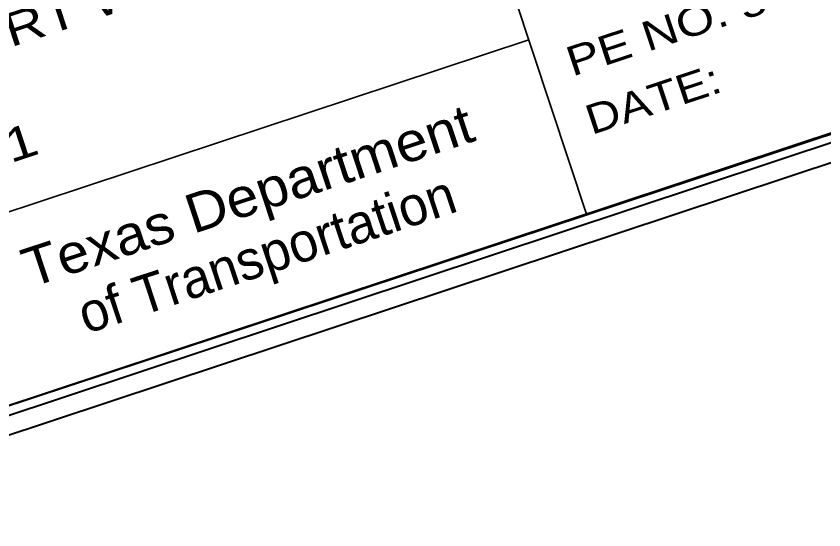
# Model space of a CAD drawing. Extents: x 2355803 to 2371254, y 6970215 to 6985302.
# Drawn here: x 2357035 to 2357464, y 6973567.6 to 6973840.5 of the extents above; entities that cross this region are included whole.
import ezdxf
from ezdxf.enums import TextEntityAlignment as Align

# ---------------------------------------------------------------- set-up
doc = ezdxf.new("R2010")
doc.units = 0
doc.header["$LTSCALE"] = 7.1
doc.layers.add('19', color=7, linetype='Continuous', lineweight=13)
doc.layers.add('8', color=7, linetype='Continuous', lineweight=13)

msp = doc.modelspace()

# ---------------------------------------------------------------- linework, layer by layer
at = {"layer": '19', "lineweight": 35}
for p, q in [((2357338.07, 6973734.835), (2357248.932, 6974004.659)), ((2357655.736, 6973839.779), (2356889.216, 6973586.555)), ((2357307.352, 6973827.819), (2356858.498, 6973679.537))]:
    msp.add_line(p, q, dxfattribs=at)
at = {"layer": '19', "lineweight": 40}
msp.add_lwpolyline([(2371235.04, 6978344.083), (2356889.216, 6973586.555), (2355819.061, 6976813.747)], dxfattribs=at)
at = {"layer": '8', "lineweight": 40}
for p, q in [((2371241.36, 6978340.911), (2356886.044, 6973580.235)), ((2371231.868, 6978337.763), (2356886.044, 6973580.235)), ((2371254, 6978334.567), (2356879.7, 6973567.595))]:
    msp.add_line(p, q, dxfattribs=at)
at = {"layer": '8', "lineweight": 35}
for p, q in [((2357338.07, 6973734.835), (2357248.932, 6974004.659)), ((2357655.736, 6973839.779), (2356889.216, 6973586.555)), ((2357307.352, 6973827.819), (2356858.498, 6973679.537))]:
    msp.add_line(p, q, dxfattribs=at)

# ---------------------------------------------------------------- texts
at = {"layer": '19'}
for s, height, width, p in [('4100 AMON CARTER BLVD., ', 17.63, 1.25, (2356839.49, 6973790.939)), ('SUITE 108 FORT WORTH , ', 17.63, 1.25, (2356848.642, 6973763.233)), ('PE NO. 58650', 15.65, 1.25, (2357330.374, 6973808.327)), ('DATE: ', 15.65, 1.2, (2357340.612, 6973777.333)), ('817-545-0891', 17.63, 1.3, (2356866.954, 6973707.809))]:
    msp.add_text(s, height=height, rotation=18.281, dxfattribs=dict(at, width=width)).set_placement(p)
at = {"layer": '19', "width": 1.1}
msp.add_text('Texas Department', height=20.67, rotation=18.281, dxfattribs=at).set_placement((2357161.156, 6973735.342), align=Align.CENTER)
at = {"layer": '19'}
msp.add_text('of Transportation', height=20.67, rotation=18.281, dxfattribs=at).set_placement((2357171.333, 6973704.292), align=Align.CENTER)
at = {"layer": '8'}
for s, height, width, p in [('4100 AMON CARTER BLVD., ', 17.63, 1.25, (2356839.49, 6973790.939)), ('SUITE 108 FORT WORTH , ', 17.63, 1.25, (2356848.642, 6973763.233)), ('PE NO. 58650', 15.65, 1.25, (2357330.374, 6973808.327)), ('DATE: ', 15.65, 1.2, (2357340.612, 6973777.333)), ('817-545-0891', 17.63, 1.3, (2356866.954, 6973707.809))]:
    msp.add_text(s, height=height, rotation=18.281, dxfattribs=dict(at, width=width)).set_placement(p)
at = {"layer": '8', "width": 1.1}
msp.add_text('Texas Department', height=20.67, rotation=18.281, dxfattribs=at).set_placement((2357161.156, 6973735.342), align=Align.CENTER)
at = {"layer": '8'}
msp.add_text('of Transportation', height=20.67, rotation=18.281, dxfattribs=at).set_placement((2357171.332, 6973704.291), align=Align.CENTER)

doc.saveas('drawing.dxf')
